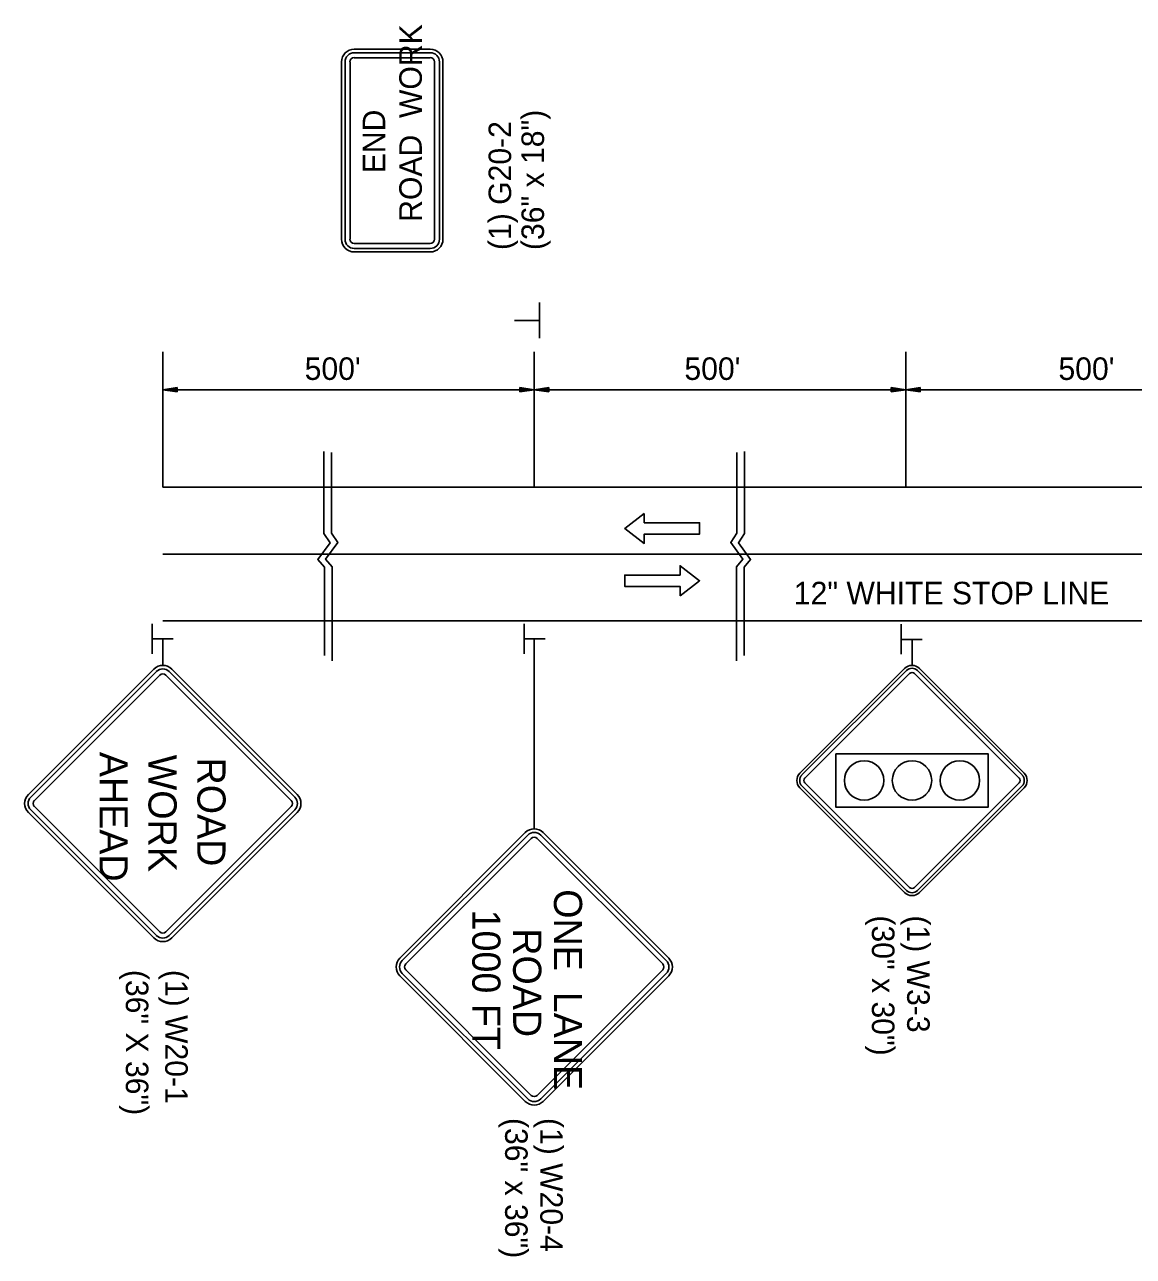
# Model space of a CAD drawing. Extents: x 1925873 to 1930787, y 596452 to 599617.
# Drawn here: x 1925873.4 to 1926168.6, y 597239.8 to 597567.9 of the extents above; entities that cross this region are included whole.
import ezdxf

# ---------------------------------------------------------------- set-up
doc = ezdxf.new("R2010")
doc.units = 0
for name, color, linetype in [('Default', 7, 'Continuous'), ('P_TC_Signs_Permanent', 7, 'Continuous'), ('P_TC_Signs_Temporary', 7, 'Continuous'), ('R_Border', 7, 'Continuous'), ('R_Striping', 7, 'Continuous')]:
    doc.layers.add(name, color=color, linetype=linetype)

msp = doc.modelspace()

# ---------------------------------------------------------------- linework, layer by layer
at = {"layer": 'Default'}
for p, q in [((1926010.41, 597493.84), (1926010.41, 597484.35)), ((1926010.27, 597489.12), (1926003.79, 597489.12)), ((1925910.15, 597480.7), (1925910.15, 597444.67)), ((1926009.05, 597480.7), (1926009.05, 597444.67)), ((1926009.05, 597480.7), (1926009.05, 597444.67)), ((1926107.95, 597480.7), (1926107.95, 597444.67)), ((1925913.99, 597471.24), (1925910.15, 597470.66)), ((1926009.05, 597470.66), (1925910.15, 597470.66)), ((1925913.99, 597470.09), (1925910.15, 597470.66)), ((1925913.99, 597471.14), (1925910.79, 597470.66)), ((1925913.99, 597470.18), (1925910.79, 597470.66)), ((1925913.99, 597471.05), (1925911.45, 597470.66)), ((1925913.99, 597470.28), (1925911.45, 597470.66)), ((1925913.99, 597470.95), (1925912.09, 597470.66)), ((1925913.99, 597470.38), (1925912.09, 597470.66)), ((1925913.99, 597470.85), (1925912.74, 597470.66)), ((1925913.99, 597470.48), (1925912.74, 597470.66)), ((1925913.99, 597470.75), (1925913.38, 597470.66)), ((1925913.99, 597470.57), (1925913.38, 597470.66)), ((1925913.99, 597470.09), (1925913.99, 597471.24)), ((1926005.21, 597471.24), (1926009.05, 597470.66)), ((1926005.21, 597470.09), (1926005.21, 597471.24)), ((1926005.21, 597471.14), (1926008.41, 597470.66)), ((1926005.21, 597471.05), (1926007.75, 597470.66)), ((1926005.21, 597470.95), (1926007.11, 597470.66)), ((1926005.21, 597470.85), (1926006.46, 597470.66)), ((1926005.21, 597470.75), (1926005.82, 597470.66)), ((1926005.21, 597470.09), (1926009.05, 597470.66)), ((1926005.21, 597470.48), (1926006.46, 597470.66)), ((1926005.21, 597470.28), (1926007.75, 597470.66)), ((1926005.21, 597470.18), (1926008.41, 597470.66)), ((1926005.21, 597470.38), (1926007.11, 597470.66)), ((1926005.21, 597470.57), (1926005.82, 597470.66)), ((1926012.89, 597471.24), (1926009.05, 597470.66)), ((1926009.05, 597470.66), (1926108.81, 597470.66)), ((1926012.89, 597470.09), (1926009.05, 597470.66)), ((1926012.89, 597471.14), (1926009.69, 597470.66)), ((1926012.89, 597470.18), (1926009.69, 597470.66)), ((1926012.89, 597471.05), (1926010.35, 597470.66)), ((1926012.89, 597470.28), (1926010.35, 597470.66)), ((1926012.89, 597470.95), (1926010.99, 597470.66)), ((1926012.89, 597470.38), (1926010.99, 597470.66)), ((1926012.89, 597470.85), (1926011.64, 597470.66)), ((1926012.89, 597470.48), (1926011.64, 597470.66)), ((1926012.89, 597470.75), (1926012.28, 597470.66)), ((1926012.89, 597470.57), (1926012.28, 597470.66)), ((1926012.89, 597470.09), (1926012.89, 597471.24)), ((1926104.11, 597471.24), (1926107.95, 597470.66)), ((1926104.11, 597470.09), (1926104.11, 597471.24)), ((1926104.11, 597471.14), (1926107.31, 597470.66)), ((1926104.11, 597471.05), (1926106.65, 597470.66)), ((1926104.11, 597470.95), (1926106.01, 597470.66)), ((1926104.11, 597470.85), (1926105.36, 597470.66)), ((1926104.11, 597470.75), (1926104.72, 597470.66)), ((1926104.11, 597470.09), (1926107.95, 597470.66)), ((1926104.11, 597470.48), (1926105.36, 597470.66)), ((1926104.11, 597470.28), (1926106.65, 597470.66)), ((1926104.11, 597470.18), (1926107.31, 597470.66)), ((1926104.11, 597470.38), (1926106.01, 597470.66)), ((1926104.11, 597470.57), (1926104.72, 597470.66)), ((1926111.79, 597471.24), (1926107.95, 597470.66)), ((1926107.95, 597470.66), (1926209.08, 597470.66)), ((1926111.79, 597470.09), (1926107.95, 597470.66)), ((1926111.79, 597471.14), (1926108.59, 597470.66)), ((1926111.79, 597470.18), (1926108.59, 597470.66)), ((1926111.79, 597471.05), (1926109.25, 597470.66)), ((1926111.79, 597470.28), (1926109.25, 597470.66)), ((1926111.79, 597470.95), (1926109.89, 597470.66)), ((1926111.79, 597470.38), (1926109.89, 597470.66)), ((1926111.79, 597470.85), (1926110.54, 597470.66)), ((1926111.79, 597470.48), (1926110.54, 597470.66)), ((1926111.79, 597470.75), (1926111.18, 597470.66)), ((1926111.79, 597470.57), (1926111.18, 597470.66)), ((1926111.79, 597470.09), (1926111.79, 597471.24)), ((1925910.15, 597444.67), (1926778.09, 597444.67)), ((1925910.15, 597426.89), (1926778.09, 597426.89)), ((1925907.3, 597400.29), (1925907.3, 597408.3)), ((1925910.15, 597409.1), (1926778.09, 597409.1)), ((1926006.38, 597400.29), (1926006.38, 597408.3)), ((1926106.77, 597400.19), (1926106.77, 597408.2)), ((1925907.42, 597404.28), (1925912.88, 597404.28)), ((1926006.49, 597404.28), (1926011.96, 597404.28)), ((1926106.89, 597404.17), (1926112.36, 597404.17))]:
    msp.add_line(p, q, dxfattribs=at)
for points in [[(1925953.04, 597454.16), (1925953.04, 597432.35), (1925954.7, 597429.88), (1925951.46, 597425.45), (1925953.17, 597423.41), (1925953.17, 597399.9)], [(1925955.08, 597453.96), (1925955.08, 597432.44), (1925956.74, 597429.97), (1925953.51, 597425.54), (1925955.21, 597423.49), (1925955.21, 597398.46)], [(1926063.02, 597453.96), (1926063.02, 597432.44), (1926061.36, 597429.97), (1926064.6, 597425.54), (1926062.89, 597423.49), (1926062.89, 597398.46)], [(1926065.07, 597454.16), (1926065.07, 597432.35), (1926063.41, 597429.88), (1926066.64, 597425.45), (1926064.94, 597423.41), (1926064.94, 597399.9)]]:
    msp.add_lwpolyline(points, dxfattribs=at)
at = {"layer": 'P_TC_Signs_Permanent'}
for p, q in [((1926079.79, 597368.57), (1926107.64, 597396.41)), ((1926080.32, 597368.04), (1926108.17, 597395.88)), ((1926108.96, 597395.09), (1926081.12, 597367.24)), ((1926138.13, 597367.24), (1926110.29, 597395.09)), ((1926111.08, 597395.88), (1926138.93, 597368.04)), ((1926111.61, 597396.41), (1926139.46, 597368.57)), ((1926081.12, 597365.92), (1926108.96, 597338.08)), ((1926110.29, 597338.08), (1926138.13, 597365.92)), ((1926107.64, 597336.75), (1926079.79, 597364.59)), ((1926108.17, 597337.28), (1926080.32, 597365.12)), ((1926138.93, 597365.12), (1926111.08, 597337.28)), ((1926139.46, 597364.59), (1926111.61, 597336.75))]:
    msp.add_line(p, q, dxfattribs=at)
msp.add_lwpolyline([(1926089.38, 597373.71), (1926089.38, 597359.46), (1926129.88, 597359.46), (1926129.88, 597373.71)], close=True, dxfattribs=at)
for centre in [(1926096.88, 597366.58), (1926109.63, 597366.58), (1926122.38, 597366.58)]:
    msp.add_circle(centre, 5.25, dxfattribs=at)
for centre, radius, start, end in [((1926109.63, 597394.42), 2.81, 45, 135), ((1926109.63, 597394.42), 2.06, 45, 135), ((1926109.63, 597394.42), 0.938, 45, 135), ((1926081.78, 597366.58), 2.81, 135, 225), ((1926137.47, 597366.58), 2.81, 315, 45), ((1926081.78, 597366.58), 2.06, 135, 225), ((1926081.78, 597366.58), 0.938, 135, 225), ((1926137.47, 597366.58), 0.938, 315, 45), ((1926137.47, 597366.58), 2.06, 315, 45), ((1926109.63, 597338.74), 2.81, 225, 315), ((1926109.63, 597338.74), 2.06, 225, 315), ((1926109.63, 597338.74), 0.938, 225, 315)]:
    msp.add_arc(centre, radius, start, end, dxfattribs=at)
at = {"layer": 'P_TC_Signs_Temporary'}
for p, q in [((1925981.37, 597561.33), (1925961.12, 597561.33)), ((1925981.37, 597560.4), (1925961.12, 597560.4)), ((1925981.37, 597559.08), (1925961.12, 597559.08)), ((1925957.75, 597557.96), (1925957.75, 597510.71)), ((1925958.69, 597557.96), (1925958.69, 597510.71)), ((1925960, 597557.96), (1925960, 597510.71)), ((1925982.5, 597510.71), (1925982.5, 597557.96)), ((1925983.81, 597510.71), (1925983.81, 597557.96)), ((1925984.75, 597510.71), (1925984.75, 597557.96)), ((1925961.12, 597509.58), (1925981.37, 597509.58)), ((1925961.12, 597508.27), (1925981.37, 597508.27)), ((1925961.12, 597507.33), (1925981.37, 597507.33)), ((1925874.35, 597362.84), (1925907.77, 597396.25)), ((1925875.02, 597362.17), (1925908.43, 597395.58)), ((1925911.88, 597395.58), (1925945.29, 597362.17)), ((1925912.54, 597396.25), (1925945.95, 597362.84)), ((1925875.95, 597361.25), (1925909.36, 597394.66)), ((1925910.95, 597394.66), (1925944.36, 597361.25)), ((1925908.43, 597325.32), (1925875.02, 597358.73)), ((1925909.36, 597326.24), (1925875.95, 597359.65)), ((1925944.36, 597359.65), (1925910.95, 597326.24)), ((1925945.29, 597358.73), (1925911.88, 597325.32)), ((1925907.77, 597324.65), (1925874.35, 597358.06)), ((1925945.95, 597358.06), (1925912.54, 597324.65)), ((1925973.25, 597319.3), (1926006.67, 597352.71)), ((1926011.44, 597352.71), (1926044.85, 597319.3)), ((1925973.92, 597318.64), (1926007.33, 597352.05)), ((1925974.85, 597317.71), (1926008.26, 597351.12)), ((1926009.85, 597351.12), (1926043.26, 597317.71)), ((1926010.78, 597352.05), (1926044.19, 597318.64)), ((1926008.26, 597282.71), (1925974.85, 597316.12)), ((1926043.26, 597316.12), (1926009.85, 597282.71)), ((1926006.67, 597281.11), (1925973.25, 597314.53)), ((1926007.33, 597281.78), (1925973.92, 597315.19)), ((1926044.19, 597315.19), (1926010.78, 597281.78)), ((1926044.85, 597314.53), (1926011.44, 597281.11))]:
    msp.add_line(p, q, dxfattribs=at)
for centre, radius, start, end in [((1925961.12, 597557.96), 3.37, 90, 180), ((1925961.12, 597557.96), 2.44, 90, 180), ((1925961.12, 597557.96), 1.13, 90, 180), ((1925981.37, 597557.96), 3.37, 360, 90), ((1925981.37, 597557.96), 2.44, 360, 90), ((1925981.37, 597557.96), 1.13, 360, 90), ((1925961.12, 597510.71), 3.37, 180, 270), ((1925961.12, 597510.71), 2.44, 180, 270), ((1925961.12, 597510.71), 1.13, 180, 270), ((1925981.37, 597510.71), 2.44, 270, 360), ((1925981.37, 597510.71), 1.13, 270, 360), ((1925981.37, 597510.71), 3.37, 270, 360), ((1925910.15, 597393.86), 3.37, 45, 135), ((1925910.15, 597393.86), 2.44, 45, 135), ((1925910.15, 597393.86), 1.12, 45, 135), ((1925876.74, 597360.45), 3.37, 135, 225), ((1925876.74, 597360.45), 2.44, 135, 225), ((1925943.56, 597360.45), 2.44, 315, 45), ((1925943.56, 597360.45), 3.37, 315, 45), ((1925876.74, 597360.45), 1.13, 135, 225), ((1925943.56, 597360.45), 1.13, 315, 45), ((1926009.05, 597350.32), 3.37, 45, 135), ((1926009.05, 597350.32), 2.44, 45, 135), ((1926009.05, 597350.32), 1.12, 45, 135), ((1925910.15, 597327.04), 1.12, 225, 315), ((1925910.15, 597327.04), 3.38, 225, 315), ((1925910.15, 597327.04), 2.44, 225, 315), ((1925975.64, 597316.91), 3.37, 135, 225), ((1926042.46, 597316.91), 3.37, 315, 45), ((1925975.64, 597316.91), 2.44, 135, 225), ((1925975.64, 597316.91), 1.13, 135, 225), ((1926042.46, 597316.91), 1.13, 315, 45), ((1926042.46, 597316.91), 2.44, 315, 45), ((1926009.05, 597283.5), 3.37, 225, 315), ((1926009.05, 597283.5), 2.44, 225, 315), ((1926009.05, 597283.5), 1.12, 225, 315)]:
    msp.add_arc(centre, radius, start, end, dxfattribs=at)
at = {"layer": 'R_Border'}
for p, q in [((1925910.15, 597404.28), (1925910.15, 597397.24)), ((1926009.05, 597404.28), (1926009.05, 597353.7)), ((1926109.63, 597404.17), (1926109.63, 597397.24))]:
    msp.add_line(p, q, dxfattribs=at)
at = {"layer": 'R_Striping'}
for points in [[(1926038.34, 597437.72), (1926033.15, 597433.72), (1926038.34, 597429.72), (1926038.34, 597432.22), (1926053.06, 597432.22), (1926053.06, 597435.22), (1926038.34, 597435.22)], [(1926047.86, 597415.78), (1926053.06, 597419.78), (1926047.86, 597423.78), (1926047.86, 597421.28), (1926033.15, 597421.28), (1926033.15, 597418.28), (1926047.86, 597418.28)]]:
    msp.add_lwpolyline(points, close=True, dxfattribs=at)

# ---------------------------------------------------------------- texts
at = {"layer": 'Default'}
msp.add_text("500'", height=6, dxfattribs=at).set_placement((1925947.92, 597473.26))
for s, p in [("500'", (1926049.03, 597473.26)), ("500'", (1926148.62, 597473.26)), ('12" WHITE STOP LINE', (1926078.17, 597413.49))]:
    msp.add_text(s, height=6, rotation=360, dxfattribs=at).set_placement(p)
at = {"layer": 'P_TC_Signs_Temporary'}
for s, height, rotation, p in [('ROAD  WORK', 6, 90, (1925979.12, 597515.37)), ('END', 6, 90, (1925969.37, 597528.3)), (' AHEAD ', 7.5, 270, (1925893.32, 597376.99)), ('WORK', 7.5, 270, (1925906.34, 597373.44)), (' ROAD ', 7.5, 270, (1925919.36, 597375.47)), ('ONE  LANE', 7.5, 270, (1926014.3, 597337.61)), ('1000 FT', 7.5, 270, (1925992.55, 597332.2)), ('ROAD', 7.5, 270, (1926003.43, 597327.22))]:
    msp.add_text(s, height=height, rotation=rotation, dxfattribs=at).set_placement(p)
at = {"layer": 'R_Border'}
for s, height, rotation, p in [('(36" x 18")', 5.9996, 90, (1926011.65, 597507.85)), ('(1) G20-2', 6, 90, (1926002.9, 597507.85)), ('(30" x 30")', 5.9996, 270, (1926098.96, 597330.64)), ('(1) W3-3', 6, 270, (1926108.33, 597330.64)), ('(36" X 36")', 6, 270, (1925900.31, 597316.14)), ('(1) W20-1', 6, 270, (1925910.79, 597316.14)), ('(36" x 36")', 5.9996, 270, (1926001.29, 597276.7)), ('(1) W20-4', 6, 270, (1926010.65, 597276.7))]:
    msp.add_text(s, height=height, rotation=rotation, dxfattribs=at).set_placement(p)

doc.saveas('drawing.dxf')
